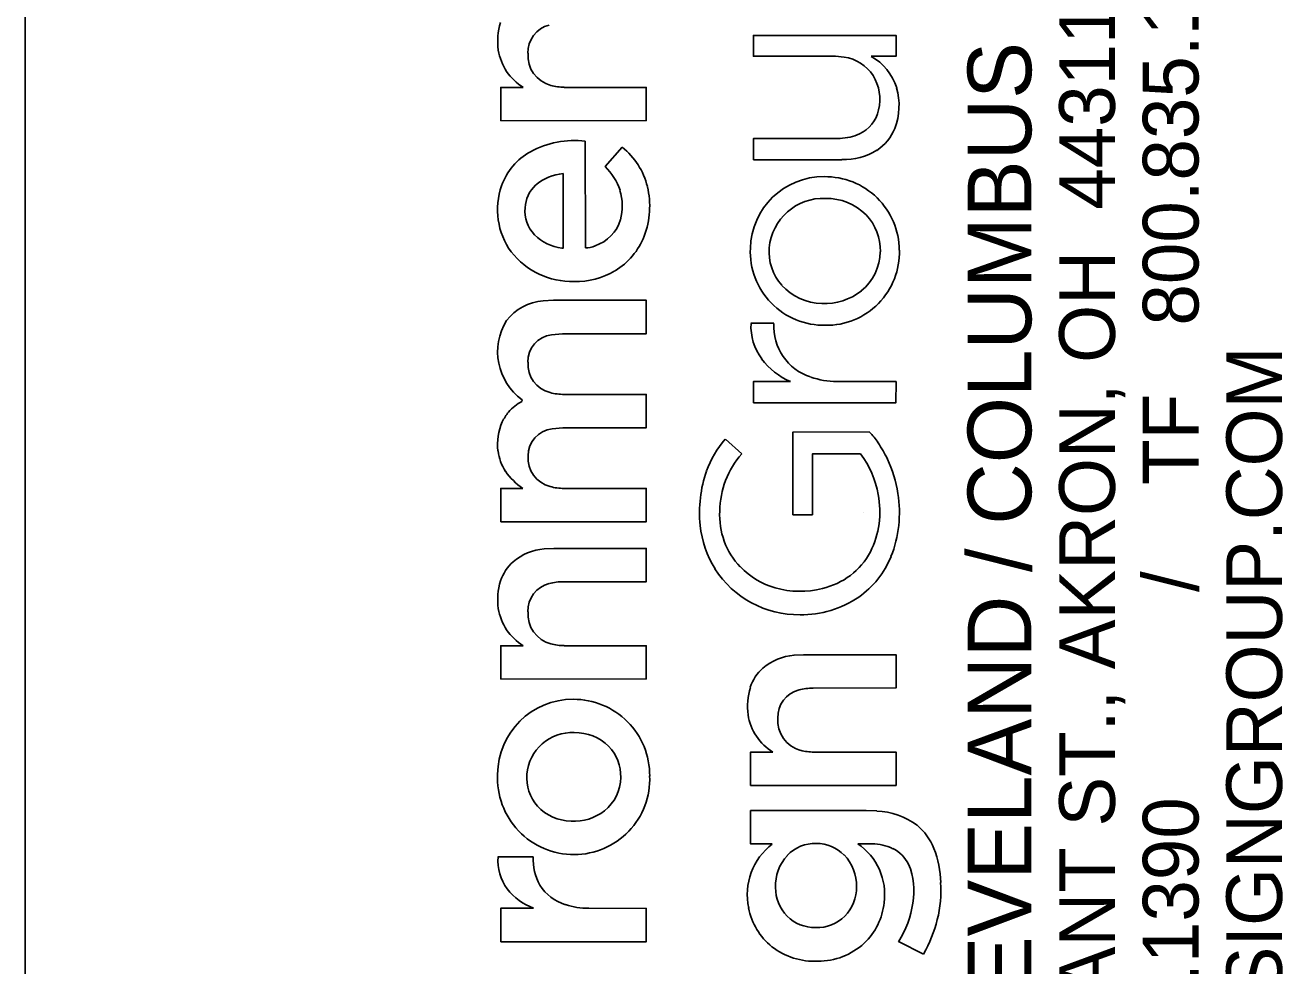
# Model space of a CAD drawing. Extents: x -4.5 to 34, y -0.4 to 22.
# Drawn here: x 32 to 33.125, y 3.594 to 4.436 of the extents above; entities that cross this region are included whole.
import ezdxf

# ---------------------------------------------------------------- set-up
doc = ezdxf.new("R2010")
doc.units = 0
doc.layers.add('SH_Border', color=7, linetype='Continuous')
doc.layers.add('SH_Data', color=7, linetype='Continuous')

msp = doc.modelspace()

# ---------------------------------------------------------------- linework, layer by layer
at = {"layer": 'SH_Border'}
msp.add_line((32, 0.5), (32, 21.5), dxfattribs=at)
at = {"layer": 'SH_Data'}
for p, q in [((32.6515, 4.408), (32.6515, 4.4267)), ((32.6515, 4.4267), (32.7791, 4.4266)), ((32.7791, 4.4266), (32.7791, 4.408)), ((32.7249, 4.408), (32.6515, 4.408)), ((32.7328, 4.4073), (32.7249, 4.408)), ((32.7791, 4.408), (32.7569, 4.408)), ((32.4254, 4.3503), (32.4254, 4.3802)), ((32.4254, 4.3802), (32.4455, 4.3802)), ((32.4822, 4.3802), (32.5557, 4.3802)), ((32.5557, 4.3802), (32.5557, 4.3504)), ((32.5557, 4.3504), (32.4254, 4.3503)), ((32.5011, 4.3321), (32.5012, 4.2366)), ((32.6515, 4.3344), (32.7291, 4.3345)), ((32.6517, 4.3154), (32.6515, 4.3344)), ((32.5188, 4.3093), (32.5342, 4.3266)), ((32.7307, 4.3154), (32.6517, 4.3154)), ((32.4814, 4.2364), (32.4814, 4.303)), ((32.4802, 4.2363), (32.4814, 4.2364)), ((32.4633, 4.1891), (32.4726, 4.1897)), ((32.4726, 4.1897), (32.5556, 4.1897)), ((32.5556, 4.1897), (32.5557, 4.1598)), ((32.6493, 4.1691), (32.6698, 4.1691)), ((32.4806, 4.1598), (32.471, 4.1588)), ((32.5557, 4.1598), (32.4806, 4.1598)), ((32.6515, 4.098), (32.6515, 4.117)), ((32.6515, 4.117), (32.6848, 4.117)), ((32.726, 4.117), (32.7791, 4.117)), ((32.7791, 4.117), (32.779, 4.098)), ((32.4444, 4.0992), (32.4446, 4.1007)), ((32.4822, 4.1055), (32.5557, 4.1055)), ((32.5557, 4.1055), (32.5557, 4.0757)), ((32.779, 4.098), (32.6515, 4.098)), ((32.4809, 4.0757), (32.4714, 4.0747)), ((32.5557, 4.0757), (32.4809, 4.0757)), ((32.6264, 4.0655), (32.6411, 4.0524)), ((32.6868, 4.0718), (32.7552, 4.0719)), ((32.6868, 3.9978), (32.6868, 4.0718)), ((32.7045, 4.0524), (32.7043, 3.9978)), ((32.7474, 4.0523), (32.7045, 4.0524)), ((32.4254, 3.9915), (32.4254, 4.0214)), ((32.4254, 4.0214), (32.4451, 4.0214)), ((32.4821, 4.0214), (32.5557, 4.0214)), ((32.5557, 4.0214), (32.5557, 3.9916)), ((32.7043, 3.9978), (32.6868, 3.9978)), ((32.75, 4), (32.75, 4)), ((32.5557, 3.9916), (32.4254, 3.9915)), ((32.4644, 3.9674), (32.4729, 3.9678)), ((32.4729, 3.9678), (32.5557, 3.9678)), ((32.5557, 3.9678), (32.5557, 3.938)), ((32.5557, 3.938), (32.4814, 3.938)), ((32.4254, 3.8509), (32.4254, 3.8807)), ((32.4254, 3.8807), (32.4455, 3.8807)), ((32.4822, 3.8807), (32.5557, 3.8807)), ((32.5557, 3.8807), (32.5557, 3.851)), ((32.6878, 3.8722), (32.6963, 3.8727)), ((32.6963, 3.8727), (32.7792, 3.8727)), ((32.7792, 3.8727), (32.7792, 3.8429)), ((32.5557, 3.851), (32.4254, 3.8509)), ((32.7792, 3.8429), (32.7048, 3.8428)), ((32.6489, 3.7557), (32.6489, 3.7855)), ((32.6489, 3.7855), (32.669, 3.7855)), ((32.7057, 3.7855), (32.7791, 3.7855)), ((32.7791, 3.7855), (32.7792, 3.7558)), ((32.7792, 3.7558), (32.6489, 3.7557)), ((32.6489, 3.7034), (32.6489, 3.7332)), ((32.6489, 3.7332), (32.7524, 3.7332)), ((32.7524, 3.7332), (32.7619, 3.7329)), ((32.6684, 3.7034), (32.6489, 3.7034)), ((32.7576, 3.7036), (32.7449, 3.7036)), ((32.423, 3.6919), (32.4545, 3.6919)), ((32.4254, 3.6159), (32.4254, 3.6458)), ((32.4254, 3.6458), (32.4547, 3.6458)), ((32.5041, 3.6458), (32.5557, 3.6457)), ((32.5557, 3.6457), (32.5556, 3.6159)), ((32.5556, 3.6159), (32.4254, 3.6159)), ((32.8036, 3.6049), (32.7812, 3.616))]:
    msp.add_line(p, q, dxfattribs=at)
for points in [[(32.7328, 4.4073), (32.7249, 4.408), (32.6515, 4.408), (32.6515, 4.4267), (32.7791, 4.4266), (32.7791, 4.408), (32.7569, 4.408)], [(32.4254, 4.3503), (32.4254, 4.3802), (32.4455, 4.3802)], [(32.4822, 4.3802), (32.5557, 4.3802), (32.5557, 4.3504), (32.4254, 4.3503)], [(32.5011, 4.3321), (32.5012, 4.2366)], [(32.7307, 4.3154), (32.6517, 4.3154), (32.6515, 4.3344), (32.7291, 4.3345)], [(32.5188, 4.3093), (32.5342, 4.3266)], [(32.4802, 4.2363), (32.4814, 4.2364), (32.4814, 4.303)], [(32.4633, 4.1891), (32.4726, 4.1897), (32.5556, 4.1897), (32.5557, 4.1598), (32.4806, 4.1598), (32.471, 4.1588)], [(32.6493, 4.1691), (32.6698, 4.1691)], [(32.6515, 4.098), (32.6515, 4.117), (32.6848, 4.117)], [(32.726, 4.117), (32.7791, 4.117), (32.779, 4.098), (32.6515, 4.098)], [(32.4444, 4.0992), (32.4446, 4.1007)], [(32.4822, 4.1055), (32.5557, 4.1055), (32.5557, 4.0757), (32.4809, 4.0757), (32.4714, 4.0747)], [(32.6264, 4.0655), (32.6411, 4.0524)], [(32.7474, 4.0523), (32.7045, 4.0524), (32.7043, 3.9978), (32.6868, 3.9978), (32.6868, 4.0718), (32.7552, 4.0719)], [(32.4254, 3.9915), (32.4254, 4.0214), (32.4451, 4.0214)], [(32.4821, 4.0214), (32.5557, 4.0214), (32.5557, 3.9916), (32.4254, 3.9915)], [(32.4644, 3.9674), (32.4729, 3.9678), (32.5557, 3.9678), (32.5557, 3.938), (32.4814, 3.938)], [(32.4254, 3.8509), (32.4254, 3.8807), (32.4455, 3.8807)], [(32.4822, 3.8807), (32.5557, 3.8807), (32.5557, 3.851), (32.4254, 3.8509)], [(32.6878, 3.8722), (32.6963, 3.8727), (32.7792, 3.8727), (32.7792, 3.8429), (32.7048, 3.8428)], [(32.6489, 3.7557), (32.6489, 3.7855), (32.669, 3.7855)], [(32.7057, 3.7855), (32.7791, 3.7855), (32.7792, 3.7558), (32.6489, 3.7557)], [(32.6684, 3.7034), (32.6489, 3.7034), (32.6489, 3.7332), (32.7524, 3.7332), (32.7619, 3.7329)], [(32.7576, 3.7036), (32.7449, 3.7036)], [(32.423, 3.6919), (32.4545, 3.6919)], [(32.4254, 3.6159), (32.4254, 3.6458), (32.4547, 3.6458)], [(32.5041, 3.6458), (32.5557, 3.6457), (32.5556, 3.6159), (32.4254, 3.6159)], [(32.8036, 3.6049), (32.7812, 3.616)]]:
    msp.add_lwpolyline(points, dxfattribs=at)
for centre, radius, start, end in [((32.4787, 4.4211), 0.056, 162.274, 187.7917), ((32.4787, 4.4211), 0.056, 162.274, 187.7917), ((32.4748, 4.4116), 0.025, 103.6868, 182.214), ((32.4748, 4.4116), 0.025, 103.6868, 182.214), ((32.4703, 4.4209), 0.0476, 188.9646, 238.6987), ((32.4703, 4.4209), 0.0476, 188.9646, 238.6987), ((32.4774, 4.4085), 0.0276, 175.5844, 255.1382), ((32.4774, 4.4085), 0.0276, 175.5844, 255.1382), ((32.7271, 4.37), 0.0377, 33.5008, 81.3295), ((32.7271, 4.37), 0.0377, 33.5008, 81.3295), ((32.7324, 4.3648), 0.0496, 17.6221, 60.3897), ((32.7324, 4.3648), 0.0496, 17.6221, 60.3897), ((32.7241, 4.3695), 0.0405, 346.5618, 31.7539), ((32.7241, 4.3695), 0.0405, 346.5618, 31.7539), ((32.4818, 4.4224), 0.0421, 254.0891, 270.5284), ((32.4818, 4.4224), 0.0421, 254.0891, 270.5284), ((32.7234, 4.3641), 0.0584, 339.162, 15.6148), ((32.7234, 4.3641), 0.0584, 339.162, 15.6148), ((32.7337, 4.3662), 0.0304, 294.6321, 348.4863), ((32.7337, 4.3662), 0.0304, 294.6321, 348.4863), ((32.739, 4.359), 0.042, 303.1039, 338.1561), ((32.739, 4.359), 0.042, 303.1039, 338.1561), ((32.4918, 4.2487), 0.0839, 83.6212, 118.2845), ((32.4918, 4.2487), 0.0839, 83.6212, 118.2845), ((32.7275, 4.3808), 0.0463, 271.952, 294.0894), ((32.7275, 4.3808), 0.0463, 271.952, 294.0894), ((32.4789, 4.2737), 0.0558, 118.8294, 160.6224), ((32.4789, 4.2737), 0.0558, 118.8294, 160.6224), ((32.494, 4.2763), 0.0644, 13.5328, 51.3627), ((32.494, 4.2763), 0.0644, 13.5328, 51.3627), ((32.7321, 4.3726), 0.0571, 268.627, 301.4778), ((32.7321, 4.3726), 0.0571, 268.627, 301.4778), ((32.4803, 4.2702), 0.0549, 19.0387, 45.4432), ((32.4803, 4.2702), 0.0549, 19.0387, 45.4432), ((32.4844, 4.2607), 0.0424, 94.0131, 130.8806), ((32.4844, 4.2607), 0.0424, 94.0131, 130.8806), ((32.7143, 4.2348), 0.0655, 89.4821, 178.7775), ((32.7143, 4.2348), 0.0655, 89.4821, 178.7775), ((32.7158, 4.2341), 0.0662, 0.4227, 90.7613), ((32.7158, 4.2341), 0.0662, 0.4227, 90.7613), ((32.487, 4.2707), 0.0644, 160.5214, 215.7815), ((32.487, 4.2707), 0.0644, 160.5214, 215.7815), ((32.477, 4.2709), 0.0298, 132.9855, 177.1802), ((32.477, 4.2709), 0.0298, 132.9855, 177.1802), ((32.4872, 4.2743), 0.047, 344.6072, 17.0067), ((32.4872, 4.2743), 0.047, 344.6072, 17.0067), ((32.4829, 4.2738), 0.0758, 339.3543, 13.3771), ((32.4829, 4.2738), 0.0758, 339.3543, 13.3771), ((32.714, 4.2324), 0.0485, 87.6883, 175.017), ((32.714, 4.2324), 0.0485, 87.6883, 175.017), ((32.7166, 4.2304), 0.0505, 44.912, 90.7591), ((32.7166, 4.2304), 0.0505, 44.912, 90.7591), ((32.4782, 4.2697), 0.0311, 175.0014, 223.2876), ((32.4782, 4.2697), 0.0311, 175.0014, 223.2876), ((32.7196, 4.2345), 0.0455, 358.3228, 43.8349), ((32.7196, 4.2345), 0.0455, 358.3228, 43.8349), ((32.499, 4.2718), 0.035, 288.0108, 343.5536), ((32.499, 4.2718), 0.035, 288.0108, 343.5536), ((32.4855, 4.2783), 0.0423, 225.0645, 262.797), ((32.4855, 4.2783), 0.0423, 225.0645, 262.797), ((32.4955, 4.2698), 0.0626, 300.9439, 338.7322), ((32.4955, 4.2698), 0.0626, 300.9439, 338.7322), ((32.4891, 4.2752), 0.0687, 217.7434, 271.6561), ((32.4891, 4.2752), 0.0687, 217.7434, 271.6561), ((32.5013, 4.2568), 0.0202, 269.7004, 294.8729), ((32.5013, 4.2568), 0.0202, 269.7004, 294.8729), ((32.7148, 4.2334), 0.0661, 177.5373, 270.9452), ((32.7148, 4.2334), 0.0661, 177.5373, 270.9452), ((32.7108, 4.2331), 0.0453, 175.5147, 221.4205), ((32.7108, 4.2331), 0.0453, 175.5147, 221.4205), ((32.7167, 4.2327), 0.0654, 269.3083, 1.6791), ((32.7167, 4.2327), 0.0654, 269.3083, 1.6791), ((32.7193, 4.2337), 0.0457, 308.9038, 359.3095), ((32.7193, 4.2337), 0.0457, 308.9038, 359.3095), ((32.492, 4.277), 0.0706, 269.2053, 300.3357), ((32.492, 4.277), 0.0706, 269.2053, 300.3357), ((32.714, 4.2373), 0.0505, 222.6626, 268.3733), ((32.714, 4.2373), 0.0505, 222.6626, 268.3733), ((32.7157, 4.2386), 0.0518, 266.5531, 308.6725), ((32.7157, 4.2386), 0.0518, 266.5531, 308.6725), ((32.4664, 4.144), 0.0452, 93.9112, 142.3072), ((32.4664, 4.144), 0.0452, 93.9112, 142.3072), ((32.4759, 4.1437), 0.0532, 148.2879, 233.9556), ((32.4759, 4.1437), 0.0532, 148.2879, 233.9556), ((32.6988, 4.1666), 0.0495, 177.1621, 216.2802), ((32.6988, 4.1666), 0.0495, 177.1621, 216.2802), ((32.7173, 4.1664), 0.0476, 176.7699, 252.1504), ((32.7173, 4.1664), 0.0476, 176.7699, 252.1504), ((32.4738, 4.135), 0.024, 96.7576, 181.6251), ((32.4738, 4.135), 0.024, 96.7576, 181.6251), ((32.4758, 4.1324), 0.026, 175.8157, 256.1672), ((32.4758, 4.1324), 0.026, 175.8157, 256.1672), ((32.7098, 4.1755), 0.0637, 216.9153, 246.8862), ((32.7098, 4.1755), 0.0637, 216.9153, 246.8862), ((32.7269, 4.1917), 0.0747, 251.1388, 269.3469), ((32.7269, 4.1917), 0.0747, 251.1388, 269.3469), ((32.4817, 4.1505), 0.045, 254.3463, 270.6103), ((32.4817, 4.1505), 0.045, 254.3463, 270.6103), ((32.4638, 4.0627), 0.0414, 117.9163, 139.243), ((32.4638, 4.0627), 0.0414, 117.9163, 139.243), ((32.4619, 4.0645), 0.0387, 139.5245, 154.847), ((32.4619, 4.0645), 0.0387, 139.5245, 154.847), ((32.4714, 4.0612), 0.0488, 156.0638, 187.3493), ((32.4714, 4.0612), 0.0488, 156.0638, 187.3493), ((32.4742, 4.0506), 0.0243, 96.5532, 179.949), ((32.4742, 4.0506), 0.0243, 96.5532, 179.949), ((32.7016, 4.0019), 0.0986, 139.7948, 159.137), ((32.7016, 4.0019), 0.0986, 139.7948, 159.137), ((32.725, 4.0394), 0.0444, 30.9891, 47.161), ((32.725, 4.0394), 0.0444, 30.9891, 47.161), ((32.6709, 4.0002), 0.1111, 25.3031, 33.9618), ((32.6709, 4.0002), 0.1111, 25.3031, 33.9618), ((32.4646, 4.0597), 0.0418, 186.5579, 213.3885), ((32.4646, 4.0597), 0.0418, 186.5579, 213.3885), ((32.4761, 4.0486), 0.0263, 175.722, 255.7863), ((32.4761, 4.0486), 0.0263, 175.722, 255.7863), ((32.699, 4.0008), 0.0775, 138.258, 179.7006), ((32.699, 4.0008), 0.0775, 138.258, 179.7006), ((32.6789, 4.001), 0.0856, 10.0751, 36.8319), ((32.6789, 4.001), 0.0856, 10.0751, 36.8319), ((32.6704, 3.9999), 0.1117, 8.8034, 25.3348), ((32.6704, 3.9999), 0.1117, 8.8034, 25.3348), ((32.4789, 4.0708), 0.0598, 214.7043, 235.6872), ((32.4789, 4.0708), 0.0598, 214.7043, 235.6872), ((32.7187, 3.9997), 0.1154, 161.1438, 185.6281), ((32.7187, 3.9997), 0.1154, 161.1438, 185.6281), ((32.4819, 4.0652), 0.0438, 253.6672, 270.1498), ((32.4819, 4.0652), 0.0438, 253.6672, 270.1498), ((32.6756, 3.9998), 0.1065, 338.2887, 9.2855), ((32.6756, 3.9998), 0.1065, 338.2887, 9.2855), ((32.6842, 4.0006), 0.0804, 333.4669, 11.0367), ((32.6842, 4.0006), 0.0804, 333.4669, 11.0367), ((32.6881, 3.9973), 0.0668, 176.6658, 223.6912), ((32.6881, 3.9973), 0.0668, 176.6658, 223.6912), ((32.6934, 3.997), 0.0899, 185.5077, 212.0129), ((32.6934, 3.997), 0.0899, 185.5077, 212.0129), ((32.4687, 3.9177), 0.0499, 94.9706, 130.2248), ((32.4687, 3.9177), 0.0499, 94.9706, 130.2248), ((32.6987, 3.9955), 0.0652, 282.8815, 331.8147), ((32.6987, 3.9955), 0.0652, 282.8815, 331.8147), ((32.4635, 3.926), 0.0402, 132.2238, 161.6823), ((32.4635, 3.926), 0.0402, 132.2238, 161.6823), ((32.6921, 3.9975), 0.0891, 212.7022, 270.714), ((32.6921, 3.9975), 0.0891, 212.7022, 270.714), ((32.6905, 4.0001), 0.0704, 224.0215, 253.88), ((32.6905, 4.0001), 0.0704, 224.0215, 253.88), ((32.6984, 3.9917), 0.0824, 305.0306, 337.6757), ((32.6984, 3.9917), 0.0824, 305.0306, 337.6757), ((32.4787, 3.9216), 0.056, 162.274, 187.7917), ((32.4787, 3.9216), 0.056, 162.274, 187.7917), ((32.4748, 3.9121), 0.025, 103.6868, 182.214), ((32.4748, 3.9121), 0.025, 103.6868, 182.214), ((32.4811, 3.892), 0.046, 89.6051, 105.3303), ((32.4811, 3.892), 0.046, 89.6051, 105.3303), ((32.6932, 4.0125), 0.0831, 254.4535, 283.9512), ((32.6932, 4.0125), 0.0831, 254.4535, 283.9512), ((32.6943, 3.9998), 0.0914, 269.3273, 304.1963), ((32.6943, 3.9998), 0.0914, 269.3273, 304.1963), ((32.4703, 3.9214), 0.0476, 188.9646, 238.6987), ((32.4703, 3.9214), 0.0476, 188.9646, 238.6987), ((32.4774, 3.909), 0.0276, 175.5844, 255.1382), ((32.4774, 3.909), 0.0276, 175.5844, 255.1382), ((32.4818, 3.9229), 0.0421, 254.0891, 270.5284), ((32.4818, 3.9229), 0.0421, 254.0891, 270.5284), ((32.6922, 3.8225), 0.0499, 94.9706, 130.2248), ((32.6922, 3.8225), 0.0499, 94.9706, 130.2248), ((32.6869, 3.8309), 0.0402, 132.2238, 161.6823), ((32.6869, 3.8309), 0.0402, 132.2238, 161.6823), ((32.7022, 3.8264), 0.056, 162.274, 187.7917), ((32.7022, 3.8264), 0.056, 162.274, 187.7917), ((32.6983, 3.8169), 0.025, 103.6868, 182.214), ((32.6983, 3.8169), 0.025, 103.6868, 182.214), ((32.7045, 3.7968), 0.046, 89.6051, 105.3303), ((32.7045, 3.7968), 0.046, 89.6051, 105.3303), ((32.4901, 3.7654), 0.0674, 89.8476, 179.6405), ((32.4901, 3.7654), 0.0674, 89.8476, 179.6405), ((32.4906, 3.7647), 0.0681, 359.5401, 90.2114), ((32.4906, 3.7647), 0.0681, 359.5401, 90.2114), ((32.6937, 3.8262), 0.0476, 188.9646, 238.6987), ((32.6937, 3.8262), 0.0476, 188.9646, 238.6987), ((32.7008, 3.8138), 0.0276, 175.5844, 255.1382), ((32.7008, 3.8138), 0.0276, 175.5844, 255.1382), ((32.4892, 3.7626), 0.0404, 87.0481, 175.5726), ((32.4892, 3.7626), 0.0404, 87.0481, 175.5726), ((32.492, 3.76), 0.043, 45.8426, 90.9801), ((32.492, 3.76), 0.043, 45.8426, 90.9801), ((32.4946, 3.7642), 0.0382, 357.8857, 44.159), ((32.4946, 3.7642), 0.0382, 357.8857, 44.159), ((32.7053, 3.8277), 0.0421, 254.0891, 270.5284), ((32.7053, 3.8277), 0.0421, 254.0891, 270.5284), ((32.4908, 3.7621), 0.0682, 176.8344, 270.4038), ((32.4908, 3.7621), 0.0682, 176.8344, 270.4038), ((32.4873, 3.7625), 0.0385, 175.1538, 221.1471), ((32.4873, 3.7625), 0.0385, 175.1538, 221.1471), ((32.4912, 3.7614), 0.0675, 270.0624, 2.3776), ((32.4912, 3.7614), 0.0675, 270.0624, 2.3776), ((32.4945, 3.7632), 0.0383, 308.2894, 359.4347), ((32.4945, 3.7632), 0.0383, 308.2894, 359.4347), ((32.4892, 3.7661), 0.0423, 223.0999, 268.8089), ((32.4892, 3.7661), 0.0423, 223.0999, 268.8089), ((32.491, 3.7679), 0.0442, 266.5651, 308.0608), ((32.491, 3.7679), 0.0442, 266.5651, 308.0608), ((32.7591, 3.6679), 0.065, 53.4034, 87.4906), ((32.7591, 3.6679), 0.065, 53.4034, 87.4906), ((32.7652, 3.6804), 0.0514, 21.6075, 50.5577), ((32.7652, 3.6804), 0.0514, 21.6075, 50.5577), ((32.7029, 3.6581), 0.0569, 127.3748, 192.2247), ((32.7029, 3.6581), 0.0569, 127.3748, 192.2247), ((32.7069, 3.6693), 0.0346, 88.473, 136.4256), ((32.7069, 3.6693), 0.0346, 88.473, 136.4256), ((32.7081, 3.6696), 0.0342, 44.2719, 90.4762), ((32.7081, 3.6696), 0.0342, 44.2719, 90.4762), ((32.7142, 3.6583), 0.0547, 352.1125, 55.923), ((32.7142, 3.6583), 0.0547, 352.1125, 55.923), ((32.7567, 3.6572), 0.0463, 65.0169, 88.8011), ((32.7567, 3.6572), 0.0463, 65.0169, 88.8011), ((32.4662, 3.6888), 0.0433, 175.8731, 216.3475), ((32.4662, 3.6888), 0.0433, 175.8731, 216.3475), ((32.5009, 3.6895), 0.0464, 176.9688, 209.6064), ((32.5009, 3.6895), 0.0464, 176.9688, 209.6064), ((32.7114, 3.666), 0.0401, 137.4674, 182.3324), ((32.7114, 3.666), 0.0401, 137.4674, 182.3324), ((32.7037, 3.666), 0.04, 358.5714, 43.5376), ((32.7037, 3.666), 0.04, 358.5714, 43.5376), ((32.7626, 3.6716), 0.0309, 26.2681, 63.803), ((32.7626, 3.6716), 0.0309, 26.2681, 63.803), ((32.7307, 3.6671), 0.0884, 1.1514, 21.3627), ((32.7307, 3.6671), 0.0884, 1.1514, 21.3627), ((32.7357, 3.6615), 0.0595, 349.3073, 23.4307), ((32.7357, 3.6615), 0.0595, 349.3073, 23.4307), ((32.7054, 3.6624), 0.1138, 329.6388, 3.26), ((32.7054, 3.6624), 0.1138, 329.6388, 3.26), ((32.4747, 3.6972), 0.0551, 218.0981, 248.7907), ((32.4747, 3.6972), 0.0551, 218.0981, 248.7907), ((32.4951, 3.6881), 0.0408, 211.9447, 253.2028), ((32.4951, 3.6881), 0.0408, 211.9447, 253.2028), ((32.7065, 3.6637), 0.0351, 178.8821, 271.0837), ((32.7065, 3.6637), 0.0351, 178.8821, 271.0837), ((32.7082, 3.664), 0.0355, 268.2788, 1.5502), ((32.7082, 3.664), 0.0355, 268.2788, 1.5502), ((32.5047, 3.7165), 0.0707, 252.4655, 269.573), ((32.5047, 3.7165), 0.0707, 252.4655, 269.573), ((32.7046, 3.657), 0.0584, 190.7518, 231.2892), ((32.7046, 3.657), 0.0584, 190.7518, 231.2892), ((32.7099, 3.6571), 0.0589, 313.742, 353.8554), ((32.7099, 3.6571), 0.0589, 313.742, 353.8554), ((32.7074, 3.6633), 0.0877, 327.3149, 351.5748), ((32.7074, 3.6633), 0.0877, 327.3149, 351.5748), ((32.7095, 3.659), 0.0605, 269.6361, 312.7088), ((32.7095, 3.659), 0.0605, 269.6361, 312.7088), ((32.7063, 3.6611), 0.0627, 232.4606, 272.5902), ((32.7063, 3.6611), 0.0627, 232.4606, 272.5902)]:
    msp.add_arc(centre, radius, start, end, dxfattribs=at)

# ---------------------------------------------------------------- texts
for s, height, p in [('800.835.1390', 0.049846, (33.0497, 4.1671)), ('450 GRANT ST., AKRON, OH  44311', 0.049846, (32.9749, 3.3374)), ('AKRON / CLEVELAND / COLUMBUS', 0.056969, (32.9001, 3.138)), ('ENVDESIGNGROUP.COM', 0.049846, (33.1244, 3.3374)), ('TF', 0.04985, (33.0497, 4.0246)), ('/  ', 0.04985, (33.0497, 3.9288)), ('330.375.1390', 0.049846, (33.0497, 3.3374))]:
    msp.add_text(s, height=height, rotation=90, dxfattribs=at).set_placement(p)

doc.saveas('drawing.dxf')
